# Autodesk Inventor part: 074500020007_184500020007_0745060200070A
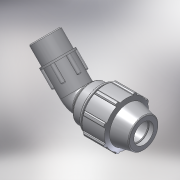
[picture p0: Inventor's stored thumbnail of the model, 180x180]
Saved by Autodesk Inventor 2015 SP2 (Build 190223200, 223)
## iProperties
Created: 2017-02
Part Number: 074500020007_184500020007_0745060200070A
Material: PVC-Piping
Description: PLASSON 45° ELBOW MALE ADAPTOR 20-3/4"
Document SubType Name: Modeling
Designer: KIM
Mass: 92.6774 g
Surface Area: 199.44 cm^2
Volume: 66.1981 cm^3
Density: 1.4 g/cm^3
Appearance: Smooth - White
Author: KIM
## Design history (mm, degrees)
derived "07450.ipt"
feature "Solid1::07450.ipt"
tag "TaggingFeature1"
body "Solid1"
other parameters: "d4" = 5.33333, "d5" = 16, "d7" = 48, "d9" = 9.14286, "d11" = 2.13333, "d13" = 120 deg, "d15" = 12 deg, "d16" = 41.76, "d18" = 1, "d19" = 35 deg, "d20" = 17.5 deg, "d21" = 44.64, "d23" = 0, "d25" = 360 deg, "d27" = 0.96, "d33" = 0.4, "d42" = 23.68, "d43" = 1.44, "d46" = 0.6, "d51" = 64, "d68" = 2.13333, "d72" = 41, "d73" = 26.441, "d74" = 18, "d75" = 30.40715, "d76" = 18.5087, "d77" = 19.8, "d80" = 0.79323, "d83" = 0, "d84" = 0, "d91" = 36, "d93" = 57, "d94" = 26.441, "d95" = 18.5087, "d96" = 9.38667, "d97" = 50 deg, "d98" = 135 deg, "d99" = 1.5, "d100" = 13.2205, "d101" = 1, "d102" = 18, "d103" = 0, "d104" = 0.72, "d106" = 360 deg, "E_" = 48, "A_" = 64, "l_" = 57, "l_2" = 18, "A_1" = 41, "R_" = 26.441
